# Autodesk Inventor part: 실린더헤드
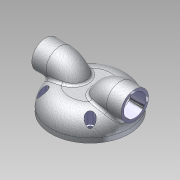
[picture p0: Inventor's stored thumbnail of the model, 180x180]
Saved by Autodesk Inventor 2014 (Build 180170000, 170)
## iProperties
Manager: KYOUNG IL JANG
Company: 한국ATC센터
Created: 2012-10
Part Number: 실린더헤드
Document SubType Name: Modeling
Density: 1 g/cm^3
Checked By: KYOUNG IL JANG
Vendor: CBT Solutions
Designer: KYOUNG IL JANG
Material: Generic
Appearance: _시험_알루미늄 표면거칠기
Author: KYOUNG IL JANG
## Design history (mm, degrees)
sketch "스케치1"
  geometry: C1 r 42.5 at (0, 0); 1 further point
  constraints: 1 centre point, 1 coincident
  dimensions: "d0" = 85 diameter of C1
extrude "돌출1" new body sketch "스케치1" distance "d1" = 25; taper "d2" = 0 deg
fillet "모깎기1" dims "d3" = 20
sketch "스케치2"
  geometry: C1 r 30 at (0, 0); 1 further point
  constraints: 1 centre point, 1 coincident
  dimensions: "d4" = 60 diameter of C1
extrude "돌출2" join sketch "스케치2" distance "d5" = 5; taper "d6" = 0 deg
node "작업 평면1"
feature "스윕1" dims "d14" = 0
feature "스윕2" dims "d15" = 0
revolve "회전1" stored, may be unused: angle "d19" = 90 deg
fillet "모깎기2" dims "d20" = 3
node "작업 평면2"
sketch "스케치6"
  geometry: L1 (0, 0)-(36.25, 0); C1 r 4.75 at (25.633, 25.633); C2 r 2.75 at (25.633, 25.633); A1 r 36.25 centre (0, 0) between (25.633, 25.633) and (36.25, 0); 1 further point
  constraints: 3 centre point, 2 coincident, 2 end point, 2 point on circle, 1 horizontal
  dimensions: "d22" = 72.5 diameter of A1; "d23" = 5.5 diameter of C2; "d24" = 9.5 diameter of C1; "d37" = 45 deg dimension on point (0, 0) C1.centre L1.end
extrude "돌출3" cut sketch "스케치6" stored distance "d25" = 5; taper "d26" = 0 deg
extrude "돌출4" cut sketch "스케치6" stored distance "d27" = 5; taper "d28" = 0 deg
chamfer "모따기1" distance "d33" = 1; stored, may be unused: second distance "d34" = 2, angle "d35" = 45 deg
node "솔리드1"
sketch "스케치3"
  geometry: L1 (-42.5, 0)-(42.5, 0) reference; L2 (-48.5, 30)-(-33, 30); L3 (-17.545, 18.141)-(-12.684, 0); A1 r 16 centre (-33, 14) between (-17.545, 18.141) and (-33, 30); 1 further point
  constraints: 4 end point, 2 point on circle, 2 tangent, 1 centre point, 1 parallel, 1 point on line
  dimensions: "d7" = 16 radius of A1; "d8" = 6 horizontal distance of L2.start L1.start; "d9" = 30 distance between parallel lines of L2 L1; "d11" = 105 deg angle of L3 L1; "d36" = 15.5 distance of L2.start L2.end
sketch "스케치4"
  geometry: C1 r 15 at (0, 0); C2 r 12 at (0, 0); 2 further points
  constraints: 2 centre point, 2 coincident
  dimensions: "d12" = 30 diameter of C1; "d13" = 3 radial gap between concentric circles of C2 C1
mirror "대칭1"
pattern_circular "원형 패턴1" dims angle "d30" = 360 deg
sketch "스케치5"
  geometry: L1 (30, -5)-(-30, -5) reference; L2 (0, -5)-(0, 10); L3 (0, 10)-(-10, 10); A1 r 15 centre (-10, -5) between (-10, 10) and (-25, -5); 1 further point
  constraints: 4 end point, 2 perpendicular, 2 point on circle, 1 centre point, 1 midpoint, 1 point on line, 1 tangent
  dimensions: "d16" = 15 distance of L2.start L2.end; "d17" = 15 radius of A1; "d18" = 5 distance of L1.end A1.end
